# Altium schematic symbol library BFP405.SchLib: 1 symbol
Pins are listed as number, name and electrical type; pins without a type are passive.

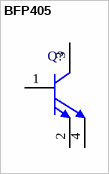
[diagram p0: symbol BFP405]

## BFP405
designator Q?
NPN Silicon RF Transistor, 4.5 V VCEO, 12 mA IC, 23 dB Gmax, SOT343, Green; Manufacturer: Infineon; PartNumber: BFP405; Gmax (typ): 23 dB; Green: yes; IC (max): 12 mA; NFmin (typ): 1.25 dB; Ptot (max): 55.0mW; VCEO (max): 4.5 V
footprint INF-SOT343_V (SOT343, 4-Leads, Body 2x1.25 mm)
pins: 1 B, 2 E, 3 C, 4 E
